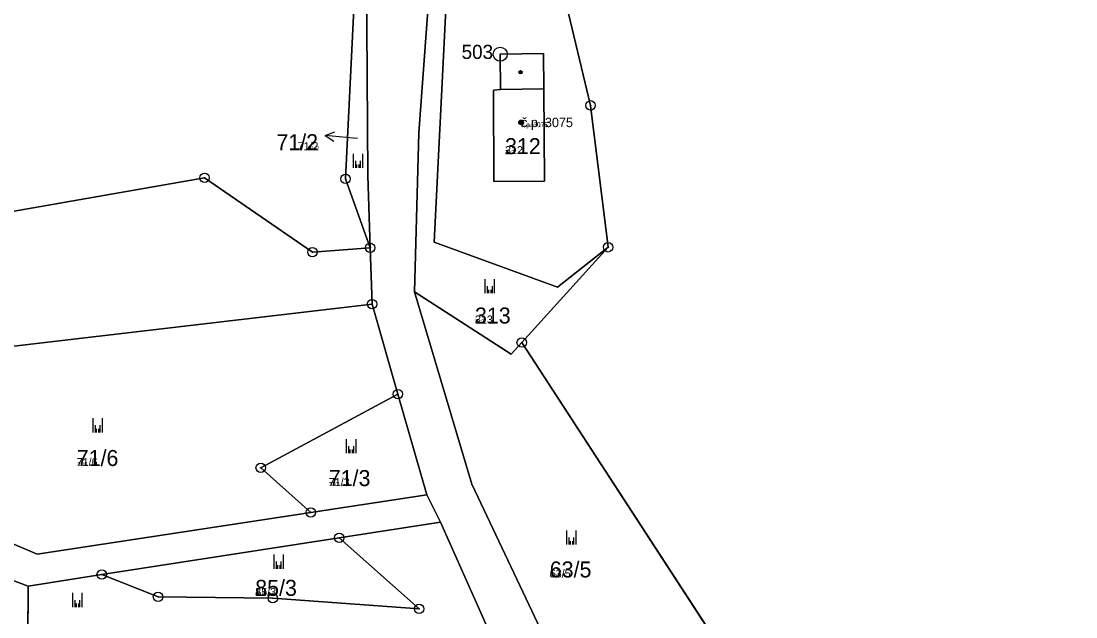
# Model space of a CAD drawing. Extents: x -759873 to -758487, y -975024 to -973516.
# Drawn here: x -759629.6 to -759517.7, y -974105.6 to -974042.3 of the extents above; entities that cross this region are included whole.
import ezdxf

# ---------------------------------------------------------------- set-up
doc = ezdxf.new("R2010")
doc.units = 0
for name, color, linetype in [('KAT_02_hranice parcel', 7, 'Continuous'), ('KAT_03_1000_st čísla parcelní', 7, 'Continuous'), ('KAT_03_1000_čísla parcelní', 7, 'Continuous'), ('KAT_03_1000_čísla popisná', 7, 'Continuous'), ('KAT_03_250_st čísla parcelní', 7, 'Continuous'), ('KAT_03_250_čísla parcelní', 7, 'Continuous'), ('KAT_03_250_čísla popisná', 7, 'Continuous'), ('KAT_03_500_st čísla parcelní', 7, 'Continuous'), ('KAT_03_500_čísla parcelní', 7, 'Continuous'), ('KAT_03_500_čísla popisná', 7, 'Continuous'), ('KAT_04_vnitřní kresba', 7, 'Continuous'), ('KAT_05_1000_značky kultur', 7, 'Continuous'), ('KAT_05_250_značky kultur', 7, 'Continuous'), ('KAT_05_500_značky kultur', 7, 'Continuous'), ('KAT_07_1000_značky budov', 7, 'Continuous'), ('KAT_07_250_značky budov', 7, 'Continuous'), ('KAT_07_500_značky budov', 7, 'Continuous'), ('KAT_11_značky bodu BP', 7, 'Continuous'), ('KAT_12_pomocná šipka', 7, 'Continuous'), ('KAT_14_plocha_budovy', 7, 'Continuous'), ('KAT_14_plocha_pozemek', 7, 'Continuous')]:
    doc.layers.add(name, color=color, linetype=linetype)

msp = doc.modelspace()

# ---------------------------------------------------------------- linework, layer by layer
at = {"layer": 'KAT_02_hranice parcel'}
for p, q in [((-759592.59, -974066.4), (-759592.39, -974072.39)), ((-759567.32, -974066.36), (-759576.5, -974076.47)), ((-759592.39, -974072.39), (-759669.1, -974081.39)), ((-759592.39, -974072.39), (-759589.64, -974081.94)), ((-759552.46, -974113.37), (-759576.5, -974076.47)), ((-759589.64, -974081.94), (-759586.56, -974092.63)), ((-759598.89, -974094.51), (-759586.56, -974092.63)), ((-759586.56, -974092.63), (-759585.13, -974095.53)), ((-759595.87, -974097.2), (-759585.13, -974095.53)), ((-759585.13, -974095.53), (-759574.33, -974119.77)), ((-759621.09, -974101.11), (-759595.87, -974097.2)), ((-759632.05, -974101.17), (-759628.88, -974102.32)), ((-759628.88, -974102.32), (-759621.09, -974101.11)), ((-759628.88, -974102.32), (-759629.25, -974156.54))]:
    msp.add_line(p, q, dxfattribs=at)
for points in [[(-759581.76, -974015.47), (-759584, -974029.8), (-759585.8, -974065.8), (-759572.7, -974070.6), (-759567.32, -974066.36)], [(-759581.76, -974015.47), (-759572.7, -974036.6), (-759569.19, -974051.29), (-759567.32, -974066.36)], [(-759593.11, -974016.5), (-759595.2, -974059.1), (-759592.59, -974066.4)], [(-759593.11, -974016.5), (-759592.85, -974058.75), (-759592.59, -974066.4)], [(-759587.88, -974071.09), (-759587.42, -974054.22), (-759584.71, -974017.13)], [(-759574.08, -974059.35), (-759579.46, -974059.39), (-759579.49, -974049.66), (-759578.74, -974049.62), (-759578.78, -974045.86), (-759574.17, -974045.8), (-759574.15, -974049.53), (-759574.08, -974059.35)], [(-759682.38, -974071.6), (-759610.17, -974058.97), (-759598.71, -974066.87), (-759592.59, -974066.4)], [(-759576.5, -974076.47), (-759577.62, -974077.7), (-759587.88, -974071.09)], [(-759587.88, -974071.09), (-759581.81, -974091.52), (-759568.77, -974119)], [(-759669.1, -974081.39), (-759627.94, -974098.94), (-759598.89, -974094.51)], [(-759589.64, -974081.94), (-759604.21, -974089.77), (-759598.89, -974094.51)], [(-759595.87, -974097.2), (-759587.39, -974104.75), (-759602.93, -974103.62), (-759615.11, -974103.47), (-759621.09, -974101.11)]]:
    msp.add_lwpolyline(points, dxfattribs=at)
at = {"layer": 'KAT_03_1000_čísla popisná'}
msp.add_circle((-759576.56, -974053.1), 0.25, dxfattribs=at)
at = {"layer": 'KAT_03_250_čísla popisná'}
msp.add_circle((-759576.56, -974053.1), 0.0625, dxfattribs=at)
at = {"layer": 'KAT_03_500_čísla popisná'}
msp.add_circle((-759576.56, -974053.1), 0.125, dxfattribs=at)
at = {"layer": 'KAT_04_vnitřní kresba'}
msp.add_line((-759578.74, -974049.62), (-759574.15, -974049.53), dxfattribs=at)
at = {"layer": 'KAT_05_1000_značky kultur'}
for p, q in [((-759594.37, -974057.93), (-759594.37, -974056.43)), ((-759593.37, -974057.93), (-759593.37, -974056.43)), ((-759580.37, -974071.24), (-759580.37, -974069.74)), ((-759579.37, -974071.24), (-759579.37, -974069.74)), ((-759622.01, -974086.01), (-759622.01, -974084.51)), ((-759621.01, -974086.01), (-759621.01, -974084.51)), ((-759595.09, -974088.22), (-759595.09, -974086.72)), ((-759594.09, -974088.22), (-759594.09, -974086.72)), ((-759571.7, -974097.92), (-759571.7, -974096.42)), ((-759570.7, -974097.92), (-759570.7, -974096.42)), ((-759602.78, -974100.48), (-759602.78, -974098.98)), ((-759601.78, -974100.48), (-759601.78, -974098.98)), ((-759624.16, -974104.56), (-759624.16, -974103.06)), ((-759623.16, -974104.56), (-759623.16, -974103.06))]:
    msp.add_line(p, q, dxfattribs=at)
at = {"layer": 'KAT_05_250_značky kultur'}
for p, q in [((-759593.99, -974057.93), (-759593.99, -974057.56)), ((-759593.74, -974057.93), (-759593.74, -974057.56)), ((-759579.99, -974071.24), (-759579.99, -974070.86)), ((-759579.74, -974071.24), (-759579.74, -974070.86)), ((-759621.63, -974086.01), (-759621.63, -974085.64)), ((-759621.38, -974086.01), (-759621.38, -974085.64)), ((-759594.71, -974088.22), (-759594.71, -974087.84)), ((-759594.46, -974088.22), (-759594.46, -974087.84)), ((-759571.32, -974097.92), (-759571.32, -974097.55)), ((-759571.07, -974097.92), (-759571.07, -974097.55)), ((-759602.4, -974100.48), (-759602.4, -974100.1)), ((-759602.15, -974100.48), (-759602.15, -974100.1)), ((-759623.78, -974104.56), (-759623.78, -974104.19)), ((-759623.53, -974104.56), (-759623.53, -974104.19))]:
    msp.add_line(p, q, dxfattribs=at)
at = {"layer": 'KAT_05_500_značky kultur'}
for p, q in [((-759594.12, -974057.93), (-759594.12, -974057.18)), ((-759593.61, -974057.93), (-759593.61, -974057.18)), ((-759580.12, -974071.24), (-759580.12, -974070.49)), ((-759579.61, -974071.24), (-759579.61, -974070.49)), ((-759621.76, -974086.01), (-759621.76, -974085.26)), ((-759621.26, -974086.01), (-759621.26, -974085.26)), ((-759594.84, -974088.22), (-759594.84, -974087.47)), ((-759594.33, -974088.22), (-759594.33, -974087.47)), ((-759571.45, -974097.92), (-759571.45, -974097.17)), ((-759570.95, -974097.92), (-759570.95, -974097.17)), ((-759602.53, -974100.48), (-759602.53, -974099.73)), ((-759602.03, -974100.48), (-759602.03, -974099.73)), ((-759623.91, -974104.56), (-759623.91, -974103.81)), ((-759623.41, -974104.56), (-759623.41, -974103.81))]:
    msp.add_line(p, q, dxfattribs=at)
at = {"layer": 'KAT_07_1000_značky budov'}
for centre in [(-759576.62, -974047.78), (-759576.57, -974053.1)]:
    msp.add_circle(centre, 0.175, dxfattribs=at)
at = {"layer": 'KAT_07_250_značky budov'}
for centre in [(-759576.61, -974047.78), (-759576.56, -974053.1)]:
    msp.add_circle(centre, 0.0437, dxfattribs=at)
at = {"layer": 'KAT_07_500_značky budov'}
for centre in [(-759576.61, -974047.78), (-759576.56, -974053.1)]:
    msp.add_circle(centre, 0.0875, dxfattribs=at)
at = {"layer": 'KAT_11_značky bodu BP'}
for centre, radius in [((-759578.78, -974045.86), 0.75), ((-759578.78, -974045.86), 0.03), ((-759569.19, -974051.29), 0.5), ((-759569.19, -974051.29), 0.0303), ((-759610.17, -974058.97), 0.5), ((-759610.17, -974058.97), 0.0303), ((-759595.2, -974059.1), 0.5), ((-759595.2, -974059.1), 0.0303), ((-759592.59, -974066.4), 0.5), ((-759567.32, -974066.36), 0.5), ((-759598.71, -974066.87), 0.5), ((-759598.71, -974066.87), 0.0303), ((-759592.59, -974066.4), 0.0303), ((-759567.32, -974066.36), 0.0303), ((-759592.39, -974072.39), 0.5), ((-759592.39, -974072.39), 0.0303), ((-759576.5, -974076.47), 0.5), ((-759576.5, -974076.47), 0.0303), ((-759589.64, -974081.94), 0.5), ((-759589.64, -974081.94), 0.0303), ((-759604.21, -974089.77), 0.5), ((-759604.21, -974089.77), 0.0303), ((-759598.89, -974094.51), 0.5), ((-759598.89, -974094.51), 0.0303), ((-759595.87, -974097.2), 0.5), ((-759595.87, -974097.2), 0.0303), ((-759621.09, -974101.11), 0.5), ((-759621.09, -974101.11), 0.0303), ((-759615.11, -974103.47), 0.5), ((-759615.11, -974103.47), 0.0303), ((-759602.93, -974103.62), 0.5), ((-759602.93, -974103.62), 0.0303), ((-759587.39, -974104.75), 0.5), ((-759587.39, -974104.75), 0.0303)]:
    msp.add_circle(centre, radius, dxfattribs=at)
at = {"layer": 'KAT_12_pomocná šipka'}
for p, q in [((-759597.38, -974054.5), (-759596.34, -974054.09)), ((-759594.39, -974054.76), (-759597.38, -974054.5)), ((-759597.38, -974054.5), (-759596.43, -974055.08)), ((-759593.94, -974054.8), (-759594.39, -974054.76))]:
    msp.add_line(p, q, dxfattribs=at)
at = {"layer": 'KAT_14_plocha_budovy'}
msp.add_lwpolyline([(-759579.46, -974059.39), (-759574.08, -974059.35), (-759574.15, -974049.53), (-759578.74, -974049.62), (-759579.49, -974049.66)], close=True, dxfattribs=at)
at = {"layer": 'KAT_14_plocha_pozemek'}
for points in [[(-759762.9, -973958.35), (-759752.64, -974049.58), (-759751.14, -974049.83), (-759710.29, -974052.52), (-759700.32, -974057.83), (-759682.38, -974071.6), (-759610.17, -974058.97), (-759598.71, -974066.87), (-759592.59, -974066.4), (-759595.2, -974059.1), (-759593.11, -974016.5)], [(-759593.11, -974016.5), (-759592.85, -974058.75), (-759592.59, -974066.4), (-759592.39, -974072.39), (-759589.64, -974081.94), (-759586.56, -974092.63), (-759585.13, -974095.53), (-759574.33, -974119.77), (-759570.22, -974124.01), (-759564.64, -974129.76), (-759561.39, -974133.11), (-759541.24, -974146.86), (-759540.34, -974147.48), (-759526.16, -974158.85), (-759523.66, -974161.11), (-759516.52, -974167.59), (-759486.83, -974191.58), (-759468.95, -974205.58), (-759465.22, -974208.76), (-759464.16, -974209.67), (-759453.16, -974219.06), (-759423.45, -974241.84)], [(-759428.19, -974233.35), (-759448.25, -974217.2), (-759461.7, -974206.38), (-759466.62, -974201.75), (-759468.82, -974199.68), (-759511.82, -974164.15), (-759531.21, -974148.13), (-759528.87, -974145.44), (-759533.76, -974140.65), (-759536.57, -974142.47), (-759537.72, -974143.21), (-759544.16, -974139.71), (-759568.77, -974119), (-759581.81, -974091.52), (-759587.88, -974071.09), (-759587.42, -974054.22), (-759584.71, -974017.13)], [(-759572.7, -974036.6), (-759569.19, -974051.29), (-759567.32, -974066.36), (-759576.5, -974076.47), (-759552.46, -974113.37), (-759549.68, -974117.63), (-759546.81, -974117.43), (-759536.2, -974132.42), (-759518.38, -974147.87), (-759504.51, -974159.89), (-759486.63, -974175.39), (-759468.43, -974180.91), (-759467.07, -974178.39), (-759455.27, -974173.93), (-759439.19, -974173.13), (-759427.95, -974173.9)], [(-759567.96, -974276.65), (-759571.75, -974271.74), (-759578.95, -974260.75), (-759586.25, -974249.97), (-759595.6, -974235.94), (-759629.25, -974156.54), (-759628.88, -974102.32), (-759632.05, -974101.17), (-759632.1, -974106.83), (-759632.14, -974110.51), (-759632.59, -974157.4), (-759597.84, -974237.11), (-759593.26, -974247.61), (-759569.36, -974281.77)]]:
    msp.add_lwpolyline(points, dxfattribs=at)
for points in [[(-759587.88, -974071.09), (-759577.62, -974077.7), (-759576.5, -974076.47), (-759567.32, -974066.36), (-759572.7, -974070.6), (-759585.8, -974065.8), (-759584, -974029.8), (-759581.76, -974015.47), (-759584.71, -974017.13), (-759587.42, -974054.22)], [(-759581.76, -974015.47), (-759584, -974029.8), (-759585.8, -974065.8), (-759572.7, -974070.6), (-759567.32, -974066.36), (-759569.19, -974051.29), (-759572.7, -974036.6)], [(-759593.11, -974016.5), (-759595.2, -974059.1), (-759592.59, -974066.4), (-759592.85, -974058.75)], [(-759574.08, -974059.35), (-759579.46, -974059.39), (-759579.49, -974049.66), (-759578.74, -974049.62), (-759578.78, -974045.86), (-759574.17, -974045.8), (-759574.15, -974049.53)], [(-759574.08, -974059.35), (-759574.15, -974049.53), (-759574.17, -974045.8), (-759578.78, -974045.86), (-759578.74, -974049.62), (-759579.49, -974049.66), (-759579.46, -974059.39)], [(-759719.88, -974055.79), (-759670.93, -974083.68), (-759632.05, -974101.17), (-759628.88, -974102.32), (-759621.09, -974101.11), (-759595.87, -974097.2), (-759585.13, -974095.53), (-759586.56, -974092.63), (-759598.89, -974094.51), (-759627.94, -974098.94), (-759669.1, -974081.39), (-759718.13, -974052.81)], [(-759592.39, -974072.39), (-759592.59, -974066.4), (-759598.71, -974066.87), (-759610.17, -974058.97), (-759682.38, -974071.6), (-759669.1, -974081.39)], [(-759552.46, -974113.37), (-759576.5, -974076.47), (-759577.62, -974077.7), (-759587.88, -974071.09), (-759581.81, -974091.52), (-759568.77, -974119)], [(-759627.94, -974098.94), (-759598.89, -974094.51), (-759604.21, -974089.77), (-759589.64, -974081.94), (-759592.39, -974072.39), (-759669.1, -974081.39)], [(-759589.64, -974081.94), (-759604.21, -974089.77), (-759598.89, -974094.51), (-759586.56, -974092.63)], [(-759623.33, -974108.59), (-759615.09, -974107), (-759603.55, -974106.84), (-759589.99, -974108.16), (-759582.78, -974111), (-759574.33, -974119.77), (-759585.13, -974095.53), (-759595.87, -974097.2), (-759587.39, -974104.75), (-759602.93, -974103.62), (-759615.11, -974103.47), (-759621.09, -974101.11), (-759628.88, -974102.32), (-759629.25, -974156.54), (-759626.33, -974155.41), (-759626.58, -974154.82), (-759627.36, -974121.2)], [(-759621.09, -974101.11), (-759615.11, -974103.47), (-759602.93, -974103.62), (-759587.39, -974104.75), (-759595.87, -974097.2)]]:
    msp.add_lwpolyline(points, close=True, dxfattribs=at)

# ---------------------------------------------------------------- texts
at = {"layer": 'KAT_03_1000_st čísla parcelní'}
msp.add_text('312', height=1.7, dxfattribs=at).set_placement((-759578.27, -974056.47))
at = {"layer": 'KAT_03_1000_čísla parcelní'}
for s, p in [('71/2', (-759602.54, -974056.05)), ('313', (-759581.46, -974074.45)), ('71/6', (-759623.74, -974089.58)), ('71/3', (-759596.98, -974091.71)), ('63/5', (-759573.52, -974101.41)), ('85/3', (-759604.79, -974103.37))]:
    msp.add_text(s, height=1.7, dxfattribs=at).set_placement(p)
at = {"layer": 'KAT_03_1000_čísla popisná'}
msp.add_text('č.p. 3075', height=1, dxfattribs=at).set_placement((-759576.56, -974053.6))
at = {"layer": 'KAT_03_250_st čísla parcelní'}
msp.add_text('312', height=0.425, dxfattribs=at).set_placement((-759578.27, -974056.47))
at = {"layer": 'KAT_03_250_čísla parcelní'}
for s, p in [('71/2', (-759599.17, -974056.05)), ('313', (-759581.46, -974074.45)), ('71/6', (-759623.74, -974089.58)), ('71/3', (-759596.98, -974091.71)), ('63/5', (-759573.52, -974101.41)), ('85/3', (-759604.79, -974103.37))]:
    msp.add_text(s, height=0.425, dxfattribs=at).set_placement(p)
at = {"layer": 'KAT_03_250_čísla popisná'}
msp.add_text('č.p. 3075', height=0.25, dxfattribs=at).set_placement((-759576.56, -974053.6))
at = {"layer": 'KAT_03_500_st čísla parcelní'}
msp.add_text('312', height=0.85, dxfattribs=at).set_placement((-759578.27, -974056.47))
at = {"layer": 'KAT_03_500_čísla parcelní'}
for s, p in [('71/2', (-759600.29, -974056.05)), ('313', (-759581.46, -974074.45)), ('71/6', (-759623.74, -974089.58)), ('71/3', (-759596.98, -974091.71)), ('63/5', (-759573.52, -974101.41)), ('85/3', (-759604.79, -974103.37))]:
    msp.add_text(s, height=0.85, dxfattribs=at).set_placement(p)
at = {"layer": 'KAT_03_500_čísla popisná'}
msp.add_text('č.p. 3075', height=0.5, dxfattribs=at).set_placement((-759576.56, -974053.6))
at = {"layer": 'KAT_11_značky bodu BP'}
msp.add_text('503', height=1.5, dxfattribs=at).set_placement((-759582.88, -974046.36))

doc.saveas('drawing.dxf')
